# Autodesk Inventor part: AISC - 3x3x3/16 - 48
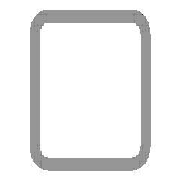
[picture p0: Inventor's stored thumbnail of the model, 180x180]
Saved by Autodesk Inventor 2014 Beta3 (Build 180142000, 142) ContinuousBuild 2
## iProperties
IsCustomPart: 1
Created: 2011-01
Part Number: AISC - 3x3x3/16 - 48
Material: Steel, Mild
Description: Tube
Document SubType Name: Modeling
Standard: ANSI
Designer: Beta-8540w
Standards Organization: ANSI
Language: en-US
Size Designation: 3x3x3/16
Categories: <MemberInstance><Categories><Category DisplayName="Structural Shapes" InternalName="089c4875-fa83-4c05-b084-43b9cc11f5ed" Mnemonic="GRDR"><CategoryParameter Dis
Stock Number: 3x3x3/16
Density: 7.86 g/cm^3
Appearance: Steel
_CCFamilyMember: 9
_CCFamilyDisplayName: ANSI AISC (Square) - Tube
_FrameMemberDoc: Frame Member File
_Version: 15.0.0
_GetPNFromCC: 1
G_L: 48.000 in
G_W: 3.000 in
G_H: 3.000 in
Author: Beta-8540w
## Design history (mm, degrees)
node "Start plane"
node "End plane"
sketch "Sketch"
  geometry: L1 (-38.1, -28.575)-(-38.1, 28.575); L2 (-28.575, 38.1)-(28.575, 38.1); L3 (38.1, 28.575)-(38.1, -28.575); L4 (28.575, -38.1)-(-28.575, -38.1); L5 (-28.575, 33.337)-(28.575, 33.338); L6 (33.338, 28.575)-(33.338, -28.575); L7 (28.575, -33.337)-(-28.575, -33.338); L8 (-33.338, -28.575)-(-33.338, 28.575); L9 (0, 56.102)-(0, -56.102) reference; L10 (-56.102, 0)-(56.102, 0) reference; A1 r 9.525 centre (-28.575, -28.575) between (-38.1, -28.575) and (-28.575, -38.1); A2 r 9.525 centre (-28.575, 28.575) between (-28.575, 38.1) and (-38.1, 28.575); A3 r 9.525 centre (28.575, 28.575) between (38.1, 28.575) and (28.575, 38.1); A4 r 9.525 centre (28.575, -28.575) between (28.575, -38.1) and (38.1, -28.575); A5 r 4.763 centre (-28.575, 28.575) between (-28.575, 33.337) and (-33.338, 28.575); A6 r 4.763 centre (28.575, 28.575) between (33.338, 28.575) and (28.575, 33.338); A7 r 4.763 centre (28.575, -28.575) between (28.575, -33.337) and (33.338, -28.575); A8 r 4.763 centre (-28.575, -28.575) between (-33.338, -28.575) and (-28.575, -33.338)
  constraints: 16 end point, 16 point on circle, 8 centre point, 8 tangent, 4 parallel, 3 equal radius, 2 perpendicular, 7 other
  dimensions: "d10" = 76.2 distance between parallel lines of L2 L4 (= G_H); "d11" = 76.2 distance between parallel lines of L1 L3 (= G_W); "d12" = 4.7625 distance between parallel lines of L3 L6 (= G_T); "d15" = 38.1 distance between parallel lines of L2 L10 (= 0.5 x d10); "d16" = 38.1 distance between parallel lines of L9 L3 (= 0.5 x d11); "d17" = 9.525 radius of A1 (= G_IR)
extrude "Body" new body sketch "Sketch" stored distance "d3" = 1219.2 (= G_L); taper "d4" = 0 deg
node "Driven Length"
  sketch "Sketch3"
    geometry: L1 (0, 0)-(10, 0) reference
    constraints: 2 end point, 1 horizontal
  workplane "Work Plane3"
  sketch "Sketch4"
    geometry: L1 (-2, 0)-(12, 0) reference; L2 (-2, 1219.2)-(12, 1219.2) reference
    dimensions: "d19" = 1219.2 distance between parallel lines of L1 L2 (derived)
body "Solid1"
other parameters: "G_W" = 76.2 [user parameter; used in 1 equation term], "G_H" = 76.2 [user parameter; used in 1 equation term], "G_T" = 4.7625 [user parameter; used in 1 equation term], "G_IR" = 9.525 [user parameter; used in 1 equation term], "G_L" = 1219.2 (= d19) [user parameter; used in 1 equation term], "G_OFFSET_START" = 0 [user parameter; used in 1 equation term], "G_OFFSET_END" = 0 [user parameter; used in 1 equation term], "d13" = 0 (computed from G_OFFSET_START), "d14" = 1219.2 (= G_OFFSET_END + B_L), "B_L" = 1219.2 [user parameter; used in 1 equation term], "d18" = 90 deg
